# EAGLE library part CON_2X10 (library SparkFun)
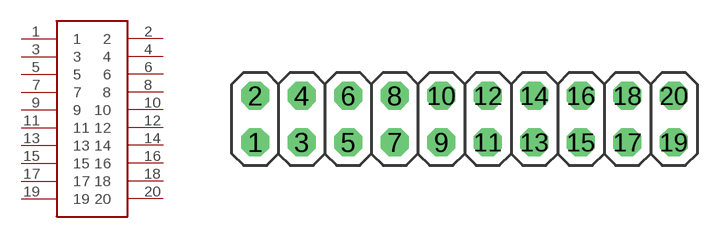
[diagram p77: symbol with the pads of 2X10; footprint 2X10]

Designator prefix -

## CON_2X10  [2X10]
1  1
2  2
3  3
4  4
5  5
6  6
7  7
8  8
9  9
10  10
11  11
12  12
13  13
14  14
15  15
16  16
17  17
18  18
19  19
20  20

## Footprint 2X10 (pad centres in mm)
PIN HEADER
drill 1.016 octagon: 1 -11.43,-1.27; 2 -11.43,1.27; 3 -8.89,-1.27; 4 -8.89,1.27; 5 -6.35,-1.27; 6 -6.35,1.27; 7 -3.81,-1.27; 8 -3.81,1.27; 9 -1.27,-1.27; 10 -1.27,1.27; 11 1.27,-1.27; 12 1.27,1.27; 13 3.81,-1.27; 14 3.81,1.27; 15 6.35,-1.27; 16 6.35,1.27; 17 8.89,-1.27; 18 8.89,1.27; 19 11.43,-1.27; 20 11.43,1.27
